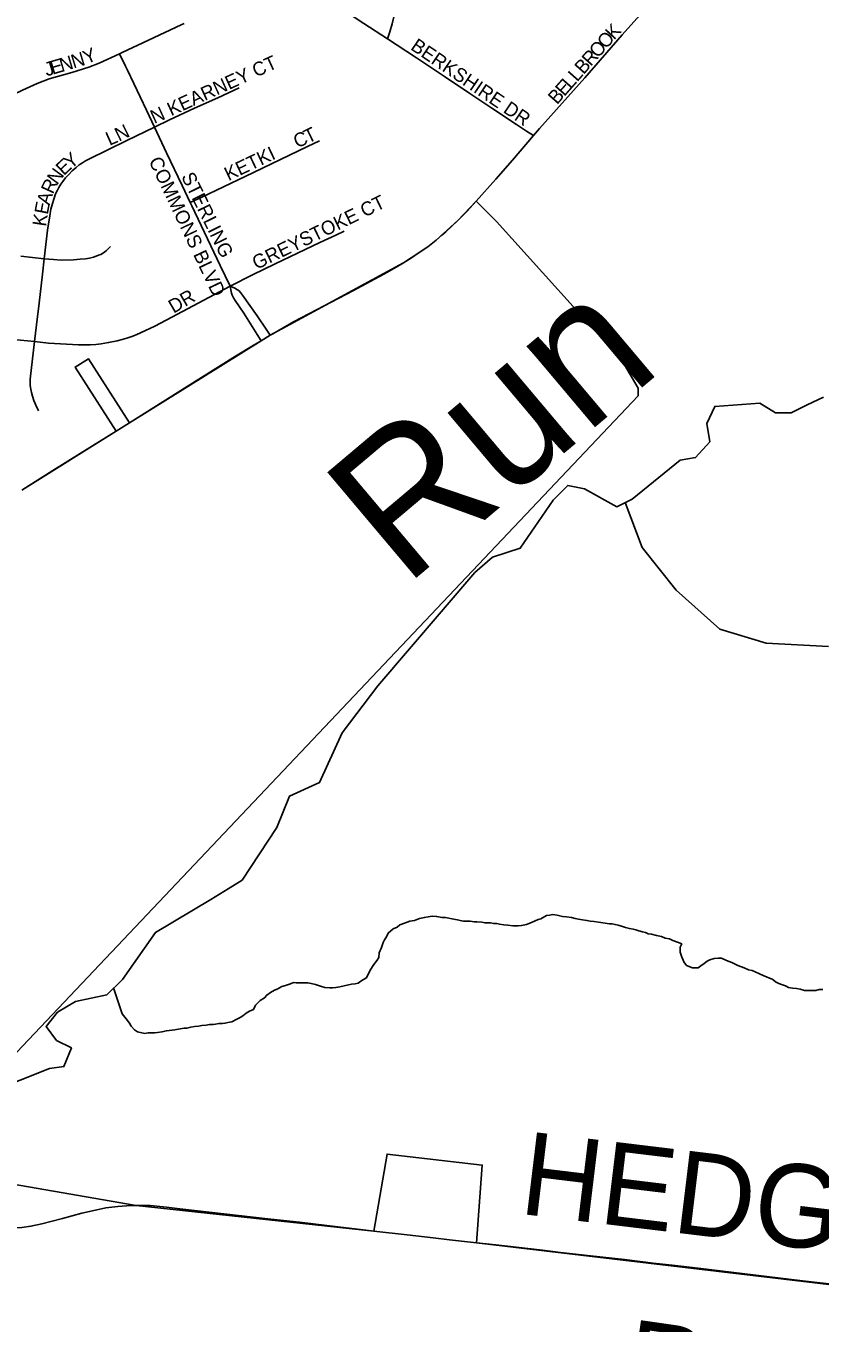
# Model space of a CAD drawing. Extents: x 1410790 to 1770854, y 448063 to 770588.
# Drawn here: x 1553501 to 1556376, y 603957 to 608653 of the extents above; entities that cross this region are included whole.
import ezdxf

# ---------------------------------------------------------------- set-up
doc = ezdxf.new("R2010")
doc.units = 0
for name, color, linetype in [('GM_X_City_Street', 7, 'Continuous'), ('GM_X_City_Street_Text', 7, 'Continuous'), ('GM_X_Corporation', 7, 'Continuous'), ('GM_X_County_Road', 7, 'Continuous'), ('GM_X_Minor_River', 7, 'Continuous'), ('GM_X_Minor_River_Text', 7, 'Continuous'), ('GM_X_Township_Road', 7, 'Continuous'), ('GM_X_Township_Road_Text', 7, 'Continuous')]:
    doc.layers.add(name, color=color, linetype=linetype)

msp = doc.modelspace()

# ---------------------------------------------------------------- linework, layer by layer
at = {"layer": 'GM_X_City_Street'}
for points in [[(1555338.3, 608255.5), (1555360.4, 608281.7), (1555524.3, 608464.7), (1555660.4, 608620.1), (1555777.6, 608753), (1555886.3, 608875.2), (1556029.1, 609036.6), (1556162.1, 609186.1), (1556246.3, 609278), (1556290.8, 609325.5)], [(1554810.9, 608605.9), (1554818.2, 608631.8), (1554826.7, 608659.7), (1554835.7, 608695.3), (1554863.6, 608815.2), (1554884, 608902.9), (1554903.5, 608995.9), (1554909.7, 609024.2)], [(1554382.2, 608888.3), (1554395.2, 608880), (1554439.9, 608851.3), (1554492.2, 608817.7), (1554538.7, 608786), (1554620.7, 608730), (1554724.6, 608661.8), (1554810.9, 608605.9)], [(1553840.3, 608552), (1553850.1, 608556.5), (1553944.9, 608601.4), (1554063.8, 608656.8), (1554073.6, 608661.5)], [(1554810.9, 608605.9), (1554915.1, 608536.7), (1555017, 608469), (1555108.9, 608407.9), (1555188.1, 608355.3), (1555277.2, 608296.1), (1555313.4, 608272.1), (1555338.3, 608255.5)], [(1553456.6, 608404.2), (1553489.1, 608420.1), (1553542.4, 608444.6), (1553585, 608460.6), (1553666.9, 608483.5), (1553729.6, 608503.6), (1553766.4, 608518.1), (1553840.3, 608552)], [(1553966.6, 608286.3), (1553938, 608347.7), (1553868.5, 608492.6), (1553861.5, 608507.4), (1553840.3, 608552)], [(1553966.6, 608286.3), (1554021.1, 608312.1), (1554111.8, 608355.1), (1554195.7, 608392.3), (1554272.9, 608428.4)], [(1553567.6, 607809.8), (1553579.3, 607913.5), (1553587.3, 607965.4), (1553591.8, 607989.5), (1553597.3, 608010.3), (1553603, 608028.9), (1553608.9, 608044.5), (1553615.1, 608057.9), (1553620.3, 608068.1), (1553627.2, 608079.3), (1553635, 608089.9), (1553645, 608102.6), (1553656.3, 608114.9), (1553669.2, 608127.7), (1553682.6, 608139.6), (1553694.6, 608149.3), (1553706, 608157.6), (1553716.7, 608164.3), (1553728.7, 608170.8), (1553867.2, 608238.1), (1553966.6, 608286.3)], [(1554095.7, 608013.4), (1554066.7, 608074.9), (1554010.2, 608193.2), (1553966.6, 608286.3)], [(1554095.7, 608013.4), (1554137.9, 608032.9), (1554189, 608057.1), (1554324.9, 608121.6), (1554520.6, 608215.9), (1554563.6, 608236.7)], [(1555131.8, 608017.8), (1555202.8, 608097.7), (1555263.3, 608166.7), (1555338.3, 608255.5)], [(1554240.7, 607710.8), (1554204.2, 607785.7), (1554101.6, 608000.8), (1554095.7, 608013.4)], [(1554240.7, 607710.8), (1554322.1, 607751.5), (1554403.6, 607791.2), (1554565.8, 607868.6), (1554623.7, 607895.4), (1554653.4, 607909.2)], [(1553567.6, 607809.8), (1553600.9, 607807), (1553629.3, 607805), (1553674.1, 607805.9), (1553698.2, 607807.8), (1553716.6, 607809.7), (1553731.3, 607812.5), (1553745.4, 607815.8), (1553755.6, 607819.1), (1553763.9, 607822.2), (1553771.9, 607825.7), (1553778.9, 607829.2), (1553786.7, 607834.5), (1553792.4, 607839.2), (1553807.6, 607854.6)], [(1553482.6, 607819.6), (1553567.6, 607809.8)], [(1553532, 607509.7), (1553539.4, 607570.9), (1553549, 607649.1), (1553560.8, 607753.6), (1553567.6, 607809.8)], [(1553532, 607509.7), (1553583.2, 607504.7), (1553691.3, 607498.3), (1553713.1, 607497.9), (1553734, 607498.3), (1553754.4, 607499.8), (1553773.1, 607501.9), (1553800.5, 607506.4), (1553831.2, 607512.7), (1553849.5, 607517.7), (1553866.6, 607522.4), (1553888.4, 607529.8), (1553902.5, 607535.4), (1553915.7, 607541.1), (1553968.5, 607565.9), (1554030.1, 607598.8), (1554240.7, 607710.8)], [(1554386, 607533), (1554371.3, 607554.4), (1554337.9, 607603.2), (1554285.4, 607678.1), (1554278.7, 607687.7), (1554272.9, 607693.2), (1554267.2, 607697.7), (1554257.6, 607703.2), (1554240.7, 607710.8)], [(1554353, 607513.2), (1554338.7, 607536), (1554289.8, 607613.2), (1554259.4, 607658.1), (1554253.2, 607668.1), (1554248.4, 607677.7), (1554246.1, 607685), (1554244.3, 607691.2), (1554240.7, 607710.8)], [(1553042.7, 607528.9), (1553204, 607534.8), (1553231.8, 607534.8), (1553253.2, 607534), (1553455.8, 607517.1), (1553532, 607509.7)], [(1553546.6, 607259.3), (1553537.6, 607279.7), (1553530.2, 607297), (1553524.9, 607312.9), (1553521.5, 607325.1), (1553518.7, 607338.2), (1553517, 607350.8), (1553516.2, 607361.3), (1553516.4, 607373.7), (1553532, 607509.7)]]:
    msp.add_lwpolyline(points, dxfattribs=at)
at = {"layer": 'GM_X_Corporation'}
for points in [[(1553188, 604643.5), (1555717.5, 607313.1), (1555717.6, 607341.5), (1555660.2, 607440.6), (1555204.7, 607945.1), (1555131.8, 608017.8), (1555065.4, 607947.7), (1554986.2, 607876.9), (1554955.8, 607853), (1554923.8, 607831.3), (1554868.5, 607795.3), (1554386, 607533), (1554353, 607513.2), (1553875.9, 607215.9), (1553727.3, 607447.9), (1553679.2, 607417.8), (1553827.6, 607185.8), (1553486.4, 606972.6)], [(1556622.4, 604071.9), (1555132.9, 604247.2), (1555153.2, 604528.9), (1554809, 604568.7), (1554760.7, 604290.2), (1553900.5, 604383.3), (1553420.4, 604466.2)]]:
    msp.add_lwpolyline(points, dxfattribs=at)
at = {"layer": 'GM_X_County_Road'}
for points in [[(1554386, 607533), (1554395, 607538.4), (1554470.5, 607581.3), (1554581.2, 607639.9), (1554684.9, 607694.2), (1554747.4, 607727.6), (1554797.4, 607754.5), (1554841.2, 607778.8), (1554868.5, 607795.3), (1554896.8, 607813.1), (1554921.9, 607830), (1554955.8, 607853), (1554986.2, 607876.9), (1555006.7, 607894.8), (1555021.8, 607907.5), (1555065.4, 607947.7), (1555097.9, 607981.2), (1555131.8, 608017.8)], [(1554353, 607513.2), (1554386, 607533)], [(1553875.9, 607215.9), (1554084.7, 607347.9), (1554259.9, 607457.1), (1554324.3, 607496.1), (1554353, 607513.2)], [(1553827.6, 607185.8), (1553875.9, 607215.9)], [(1553486.4, 606972.6), (1553598.9, 607043.2), (1553707.9, 607110.4), (1553827.6, 607185.8)]]:
    msp.add_lwpolyline(points, dxfattribs=at)
at = {"layer": 'GM_X_Minor_River'}
for points in [[(1553372.6, 604793.8), (1553586.5, 604878.3), (1553638.8, 604885.5), (1553666, 604953.2), (1553612.3, 604980.2), (1553575.1, 605030.9), (1553616.1, 605082.3), (1553680.9, 605121.3), (1553793.6, 605145.5), (1553850.7, 605200.6), (1553969.9, 605371), (1554170.4, 605489.9), (1554233.2, 605528.9), (1554283.8, 605560.1), (1554409.4, 605750.5), (1554455.4, 605864), (1554564.5, 605914.2), (1554645.8, 606093.3), (1554775, 606263.5), (1555126.9, 606674.6), (1555189.9, 606729.6), (1555290.7, 606762), (1555410, 606936.4), (1555463, 606989.6), (1555523, 606976.6), (1555640.1, 606912.4), (1555696.7, 606939.5), (1555869.6, 607080.9), (1555925.8, 607090), (1555976.9, 607147.3), (1555966.1, 607213.6), (1555995.2, 607275.3), (1556157.8, 607286.5), (1556215.3, 607251.5), (1556271.4, 607252.5), (1556330.1, 607281.6), (1556388.7, 607308.7)], [(1555670.9, 606927.1), (1555731.8, 606764.5), (1555855.5, 606610), (1556013.5, 606468.9), (1556181, 606417.9), (1556407.3, 606406)], [(1553818.7, 605170.6), (1553850.3, 605076.6), (1553864.1, 605058.4), (1553876, 605042.3), (1553881.9, 605032.2), (1553893.8, 605018.1), (1553905.8, 605012), (1553931.7, 605005.8), (1553943.8, 605007.7), (1553953.8, 605007.6), (1553967.8, 605007.5), (1553977.8, 605009.4), (1553993.8, 605011.2), (1554009.9, 605015.1), (1554029.9, 605016.9), (1554039.9, 605018.8), (1554060, 605022.7), (1554074, 605024.6), (1554084, 605024.5), (1554098, 605028.4), (1554112.1, 605030.3), (1554126.1, 605032.1), (1554138.1, 605034), (1554154.1, 605035.9), (1554166.2, 605037.8), (1554178.2, 605037.7), (1554188.2, 605039.6), (1554200.2, 605041.5), (1554212.2, 605041.4), (1554222.2, 605043.3), (1554232.3, 605045.2), (1554246.3, 605047.1), (1554264.4, 605057), (1554276.4, 605062.9), (1554286.5, 605068.8), (1554298.6, 605078.7), (1554310.6, 605086.6), (1554324.7, 605092.5), (1554332.8, 605108.5), (1554349, 605124.4), (1554365.1, 605134.3), (1554373.2, 605144.2), (1554387.2, 605154.1), (1554401.3, 605162), (1554411.4, 605165.9), (1554427.4, 605175.8), (1554441.5, 605179.7), (1554459.5, 605185.5), (1554469.6, 605189.5), (1554479.6, 605189.4), (1554489.6, 605189.3), (1554505.6, 605189.2), (1554521.6, 605189), (1554533.6, 605186.9), (1554549.6, 605182.8), (1554567.5, 605176.6), (1554583.5, 605172.4), (1554601.5, 605170.3), (1554611.5, 605170.2), (1554623.5, 605172.1), (1554637.6, 605174), (1554653.6, 605177.8), (1554679.7, 605183.6), (1554693.7, 605185.5), (1554703.7, 605187.4), (1554713.8, 605195.4), (1554723.8, 605201.3), (1554733.9, 605207.2), (1554748.1, 605235.1), (1554760.3, 605255.1), (1554772.4, 605271), (1554778.5, 605281), (1554780.7, 605297), (1554788.8, 605316.9), (1554795, 605334.9), (1554799.1, 605344.9), (1554807.1, 605354.8), (1554813.3, 605368.8), (1554831.4, 605384.7), (1554845.5, 605390.6), (1554855.5, 605398.5), (1554871.6, 605404.4), (1554891.7, 605412.2), (1554907.7, 605414.1), (1554925.8, 605421.9), (1554943.8, 605425.8), (1554957.8, 605427.7), (1554971.9, 605429.6), (1554987.9, 605429.4), (1555007.8, 605425.2), (1555019.8, 605425.1), (1555031.8, 605423), (1555043.8, 605420.9), (1555063.8, 605416.7), (1555073.8, 605414.7), (1555085.8, 605412.5), (1555109.8, 605412.3), (1555123.8, 605410.2), (1555133.8, 605410.1), (1555151.8, 605408)], [(1555151.8, 605408), (1555163.8, 605405.9), (1555173.8, 605405.8), (1555183.8, 605405.7), (1555193.8, 605403.6), (1555205.8, 605403.5), (1555215.8, 605401.4), (1555231.8, 605399.3), (1555245.8, 605397.1), (1555263.8, 605395), (1555273.8, 605394.9), (1555283.8, 605394.8), (1555295.8, 605396.7), (1555313.8, 605400.5), (1555325.9, 605404.5), (1555342, 605412.3), (1555356, 605418.2), (1555366, 605420.1), (1555386.1, 605432), (1555398.2, 605433.9), (1555408.2, 605435.8), (1555424.2, 605433.7), (1555434.2, 605431.6), (1555444.2, 605429.5), (1555458.1, 605427.4), (1555476.1, 605425.2), (1555490.1, 605421.1), (1555502.1, 605419), (1555516.1, 605416.8), (1555532.1, 605414.7), (1555544.1, 605412.6), (1555558.1, 605410.5), (1555574.1, 605408.3), (1555614.1, 605402), (1555624.1, 605401.9), (1555634, 605399.8), (1555646, 605397.7), (1555658, 605393.6), (1555672, 605389.4), (1555686, 605385.3), (1555699.9, 605383.2), (1555709.9, 605381.1), (1555719.9, 605377), (1555733.9, 605372.9), (1555743.9, 605370.8), (1555753.9, 605366.7), (1555765.8, 605364.6), (1555783.8, 605360.4), (1555801.8, 605356.2), (1555815.8, 605350.1), (1555831.8, 605348), (1555843.7, 605341.9), (1555859.7, 605335.7), (1555875.6, 605329.6), (1555869.5, 605317.6), (1555869.4, 605299.6), (1555875.3, 605285.5), (1555883.1, 605265.4), (1555893, 605251.3), (1555915, 605243.1), (1555925, 605243), (1555935, 605242.9), (1555945, 605250.8), (1555957.1, 605258.7), (1555967.2, 605266.7), (1555977.2, 605272.6), (1555993.3, 605276.4), (1556007.3, 605278.3), (1556019.3, 605278.2), (1556037.3, 605270.1), (1556057.2, 605261.9), (1556079.1, 605251.7), (1556101.1, 605243.5), (1556117, 605235.3), (1556131, 605233.2), (1556141, 605229.1), (1556156.9, 605220.9), (1556170.9, 605214.8), (1556204.8, 605200.5), (1556214.8, 605192.4), (1556226.7, 605186.3), (1556236.7, 605182.2), (1556250.7, 605178), (1556262.6, 605171.9), (1556276.6, 605169.8), (1556290.6, 605167.7), (1556304.6, 605165.5), (1556320.6, 605161.4), (1556334.6, 605161.3), (1556346.6, 605161.2), (1556360.6, 605161.1), (1556372.6, 605165), (1556386.6, 605164.8)]]:
    msp.add_lwpolyline(points, dxfattribs=at)
at = {"layer": 'GM_X_Township_Road'}
for points in [[(1553004.9, 604485.1), (1553022.2, 604475.5), (1553044.6, 604459.7), (1553112.8, 604406.8), (1553143.6, 604385.5), (1553178.7, 604363.8), (1553206.1, 604349.1), (1553235.1, 604336.9), (1553267.3, 604324.3), (1553303.7, 604314.3), (1553338, 604307.4), (1553373.2, 604302.2), (1553409.6, 604299.5), (1553448.7, 604300.4), (1553486.5, 604302.6), (1553519.4, 604307.8), (1553558.5, 604316), (1553633.3, 604336.3), (1553703.2, 604354.5), (1553764.1, 604368.8), (1553791.1, 604374.1), (1553833.7, 604379.4), (1553865.8, 604382), (1553900.5, 604383.3)], [(1553900.5, 604383.3), (1553951.2, 604382.2), (1554010, 604377), (1554058.8, 604371.3), (1554377.4, 604334.5), (1554491.4, 604322.5), (1554631.1, 604305.7), (1554722.3, 604294.7), (1554760.7, 604290.2)], [(1554760.7, 604290.2), (1554881.1, 604276.1), (1554975.6, 604265.2), (1555034.3, 604258.5), (1555132.9, 604247.2)], [(1555132.9, 604247.2), (1555202, 604240), (1555371.6, 604221.2), (1555436.7, 604212.8), (1555534.4, 604202), (1555668.1, 604187.1), (1555772.3, 604174.1), (1555840.7, 604166.3), (1555935.3, 604156.3), (1556143.7, 604130.6), (1556313.1, 604110.2), (1556440.2, 604095.2), (1556580.1, 604077.2), (1556622.4, 604071.9), (1556690.9, 604063.8), (1556736.5, 604056.9), (1556768.9, 604050.6), (1556797.8, 604042.8), (1556822.9, 604033.8), (1556841.1, 604025.2), (1556877.1, 604005.5), (1556890.1, 603997.8)]]:
    msp.add_lwpolyline(points, dxfattribs=at)

# ---------------------------------------------------------------- texts
at = {"layer": 'GM_X_City_Street_Text'}
for s, rotation, p in [('K', 47.7983, (1555630.6, 608599.5)), ('BERKSHIRE DR', 325.8397, (1554890.7, 608569.4)), ('O', 48.5891, (1555601.6, 608566.7)), ('N', 17.0367, (1553673.5, 608498.2)), ('Y', 22.5183, (1553720.5, 608512.9)), ('R', 48.5819, (1555546.3, 608504)), ('O', 48.557, (1555572.5, 608533.7)), ('J', 16.4857, (1553576, 608469.4)), ('E', 16.4558, (1553597.1, 608475.6)), ('N', 16.4612, (1553630.8, 608485.6)), ('N KEARNEY CT', 24.5367, (1553966.1, 608297.3)), ('B', 48.5819, (1555520.1, 608474.3)), ('E', 48.557, (1555450.2, 608395.1)), ('L', 48.557, (1555473.5, 608421.5)), ('L', 48.557, (1555496.8, 608447.9)), ('B', 48.5742, (1555424, 608365.4)), ('N', 25.8563, (1553838, 608233.1)), ('T', 25.9044, (1554522.2, 608226)), ('L', 23.7045, (1553803.9, 608218.1)), ('C', 21.9231, (1554482, 608209.7)), ('Y', 40.1889, (1553663.4, 608132.3)), ('COMMONS BLVD', 295.4415, (1553944.6, 608164.5)), ('KETKI', 25.3491, (1554234.6, 608090.5)), ('N', 53.9999, (1553614.1, 608074.9)), ('E', 43.2994, (1553638.3, 608108.7)), ('R', 65.2486, (1553598.8, 608041.2)), ('STERLING', 296.1893, (1554062.4, 608107.9)), ('A', 73.0098, (1553586.6, 608000.8)), ('GREYSTOKE CT', 25.8525, (1554335.8, 607769.3)), ('E', 79.1454, (1553580.3, 607967.6)), ('K', 81.4433, (1553573.8, 607924.6)), ('DR', 30.4678, (1554035.9, 607610.5))]:
    msp.add_text(s, height=50, rotation=rotation, dxfattribs=at).set_placement(p)
at = {"layer": 'GM_X_Minor_River_Text'}
msp.add_text('Run', height=499.98, rotation=40.1306, dxfattribs=at).set_placement((1554872.7, 606619.2))
at = {"layer": 'GM_X_Township_Road_Text'}
for s, rotation, p in [('HEDGES', 353.1096, (1555282.8, 604353.5)), ('R', 351.8782, (1555653.1, 603675.2))]:
    msp.add_text(s, height=300, rotation=rotation, dxfattribs=at).set_placement(p)

doc.saveas('drawing.dxf')
